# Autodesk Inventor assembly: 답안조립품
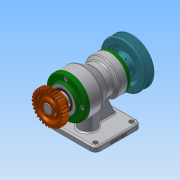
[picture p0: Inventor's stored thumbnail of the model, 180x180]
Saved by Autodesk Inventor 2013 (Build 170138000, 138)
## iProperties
Created: 2019-01
Part Number: 답안조립품
Document SubType Name: Assembly
Designer: Administrator
Author: Administrator
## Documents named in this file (15)
- C:\Users\Administrator\Desktop\490107V1050\답안조립품.iam
- C:\Users\Administrator\Desktop\490107V1050\본체.ipt
- C:\Users\Administrator\Desktop\490107V1050\앞커버.ipt
- C:\Users\Administrator\Desktop\490107V1050\뒤커버.ipt
- C:\Users\Administrator\Desktop\490107V1050\베어링 6203.ipt
- C:\Users\Administrator\Desktop\490107V1050\베어링 6205.ipt
- C:\Users\Administrator\Desktop\490107V1050\오일 실 17 30 8.ipt
- C:\Users\Administrator\Desktop\490107V1050\오일 실 25 38 8.ipt
- C:\Users\Administrator\Desktop\490107V1050\축.ipt
- C:\Users\Administrator\Desktop\490107V1050\키 5 x 5 x 20.ipt
- C:\Users\Administrator\Desktop\490107V1050\키 6 x 6 x 18.ipt
- C:\Users\Administrator\Desktop\490107V1050\스퍼기어.ipt
- C:\Users\Administrator\Desktop\490107V1050\멈춤나사 M3.ipt
- C:\Users\Administrator\Desktop\490107V1050\V-벨트풀리.ipt
- C:\Users\Administrator\Desktop\490107V1050\볼트 M4.ipt
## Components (1 placed, 1 different names)
1. V-벨트풀리:1
